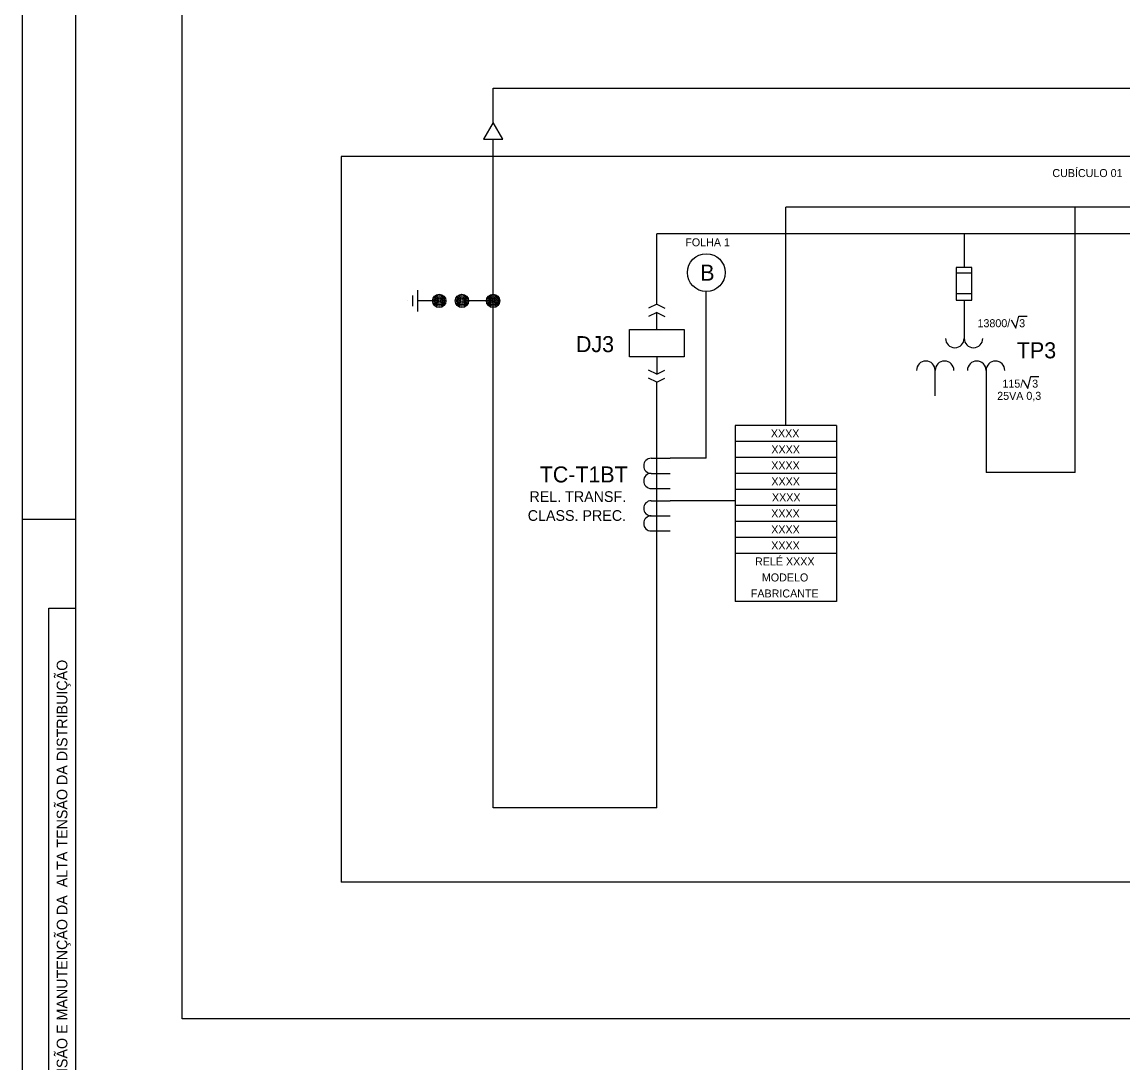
# Model space of a CAD drawing. Extents: x 563 to 1404, y 358 to 952.
# Drawn here: x 562.6 to 768.9, y 553.1 to 748.2 of the extents above; entities that cross this region are included whole.
import ezdxf

# ---------------------------------------------------------------- set-up
doc = ezdxf.new("R2010")
doc.units = 0
doc.layers.add('13', color=7, linetype='Continuous')
doc.layers.add('New Level (0)', color=7, linetype='Continuous')

# ---------------------------------------------------------------- blocks, each defined once
blk = doc.blocks.new('_U3')
for p, q in [((-1.47, 0.42), (-0.62, -1.12)), ((-0.62, -1.12), (-0.07, 1.12)), ((-0.07, 1.12), (1.47, 1.12))]:
    blk.add_line(p, q)

msp = doc.modelspace()

# ---------------------------------------------------------------- linework, layer by layer
for p, q in [((650.86, 729.31), (650.86, 735.75)), ((650.86, 735.75), (799.81, 735.75)), ((650.86, 729.31), (649.05, 726.21)), ((652.67, 726.21), (650.86, 729.31)), ((649.05, 726.21), (652.67, 726.21)), ((649.05, 726.21), (652.67, 726.21)), ((1296.89, 722.95), (622.37, 722.95)), ((622.37, 722.95), (622.37, 586.96)), ((1280.96, 713.45), (705.72, 713.45)), ((705.72, 672.55), (705.72, 713.45)), ((759.97, 663.73), (759.97, 713.45)), ((1256.75, 708.46), (681.52, 708.46)), ((681.52, 695.25), (681.52, 708.46)), ((739.14, 708.46), (739.14, 702.17)), ((740.6, 701.05), (737.67, 701.05)), ((636.77, 693.89), (636.77, 697.89)), ((690.82, 666.38), (690.82, 697.64)), ((634.77, 695.89), (634.77, 695.89)), ((635.77, 696.89), (635.77, 694.89)), ((640.77, 695.89), (636.77, 695.89)), ((640.77, 695.89), (636.77, 695.89)), ((650.86, 695.89), (646.27, 695.89)), ((740.6, 697.18), (737.67, 697.18)), ((739.14, 696.05), (739.14, 688.86)), ((681.52, 690.5), (681.52, 693.73)), ((681.52, 690.5), (681.52, 693.73)), ((676.4, 685.38), (676.4, 690.5)), ((676.4, 690.5), (686.64, 690.5)), ((686.64, 690.5), (686.64, 685.38)), ((686.64, 685.38), (676.4, 685.38)), ((681.52, 685.38), (681.52, 682.16)), ((733.71, 678.08), (733.71, 682.86)), ((743.25, 682.86), (743.25, 663.73)), ((681.52, 600.87), (681.52, 680.63)), ((715.21, 672.55), (696.23, 672.55)), ((696.23, 672.55), (696.23, 639.55)), ((715.21, 672.55), (715.21, 639.55)), ((715.21, 669.55), (696.23, 669.55)), ((715.21, 666.55), (696.23, 666.55)), ((680.5, 666.38), (684.03, 666.38)), ((690.82, 666.38), (684.03, 666.38)), ((680.5, 663.55), (684.03, 663.55)), ((715.21, 663.55), (696.23, 663.55)), ((759.97, 663.73), (743.25, 663.73)), ((680.5, 660.72), (684.03, 660.72)), ((715.21, 660.55), (696.23, 660.55)), ((680.5, 658.42), (684.03, 658.42)), ((696.23, 658.42), (684.03, 658.42)), ((715.21, 657.55), (696.23, 657.55)), ((680.5, 655.59), (684.03, 655.59)), ((715.21, 654.55), (696.23, 654.55)), ((715.21, 654.55), (696.23, 654.55)), ((680.5, 652.76), (684.03, 652.76)), ((715.21, 651.55), (696.23, 651.55)), ((715.21, 648.55), (696.23, 648.55)), ((715.21, 639.55), (696.23, 639.55)), ((1296.89, 586.96), (622.37, 586.96))]:
    msp.add_line(p, q)
msp.add_lwpolyline([(681.52, 600.87), (650.86, 600.87), (650.86, 726.21)])
msp.add_lwpolyline([(740.6, 702.17), (737.67, 702.17), (737.67, 696.05), (740.6, 696.05)], close=True)
for centre, radius in [((640.77, 695.89), 1.25), ((640.77, 695.89), 1), ((640.77, 695.89), 0.75), ((640.77, 695.89), 0.5), ((640.77, 695.89), 0.25), ((645.02, 695.89), 1.25), ((645.02, 695.89), 1), ((645.02, 695.89), 0.75), ((645.02, 695.89), 0.5), ((645.02, 695.89), 0.25), ((650.86, 695.89), 1.25), ((650.86, 695.89), 1), ((650.86, 695.89), 0.75), ((650.86, 695.89), 0.5), ((650.86, 695.89), 0.25)]:
    msp.add_circle(centre, radius)
for centre, radius, start, end in [((737.39, 688.86), 1.75, 180, 360), ((740.89, 688.86), 1.75, 180, 360), ((731.96, 682.86), 1.75, 0, 180), ((735.46, 682.86), 1.75, 0, 180), ((741.5, 682.86), 1.75, 0, 180), ((745, 682.86), 1.75, 0, 180), ((680.5, 664.97), 1.42, 90, 270), ((680.5, 662.14), 1.42, 90, 270), ((680.5, 657.01), 1.42, 90, 270), ((680.5, 654.18), 1.42, 90, 270)]:
    msp.add_arc(centre, radius, start, end)
at = {"layer": '13'}
for p, q in [((681.52, 695.25), (679.99, 694.49)), ((681.52, 693.73), (679.99, 692.97)), ((681.52, 695.25), (683.05, 694.49)), ((681.52, 693.73), (683.05, 692.97)), ((681.52, 682.16), (679.99, 682.92)), ((681.52, 680.63), (679.99, 681.4)), ((681.52, 682.16), (683.05, 682.92)), ((681.52, 680.63), (683.05, 681.4))]:
    msp.add_line(p, q, dxfattribs=at)
at = {"layer": 'New Level (0)'}
for p, q in [((562.58, 951.96), (562.58, 357.96)), ((562.58, 951.96), (562.58, 357.96)), ((572.58, 941.96), (572.58, 367.96)), ((572.58, 941.96), (572.58, 367.96)), ((562.58, 654.96), (572.58, 654.96)), ((567.58, 638.29), (572.58, 638.29)), ((567.58, 434.97), (567.58, 638.29))]:
    msp.add_line(p, q, dxfattribs=at)
msp.add_lwpolyline([(592.61, 760.21), (1379.09, 760.21), (1379.09, 561.33), (592.61, 561.33)], close=True, dxfattribs=at)
msp.add_circle((690.82, 701.18), 3.54, dxfattribs=at)

# ---------------------------------------------------------------- block references
for p in [(749.45, 691.92), (751.68, 680.6)]:
    msp.add_blockref('_U3', p)

# ---------------------------------------------------------------- texts
for s, height, p in [('CUBÍCULO 01', 1.5, (755.67, 719.09)), ('FOLHA 1', 1.5, (686.88, 706.11)), ('B', 3, (689.69, 699.68)), ('13800/   3', 1.5, (741.64, 690.95)), ('DJ3', 3, (666.39, 686.28)), ('TP3', 3, (749.02, 685.12)), ('115/   3', 1.5, (746.31, 679.63)), ('25VA 0,3', 1.5, (745.33, 677.34)), ('XXXX', 1.5, (702.91, 670.3)), ('XXXX', 1.5, (703.01, 667.3)), ('TC-T1BT', 3, (659.6, 661.86)), ('XXXX', 1.5, (702.98, 664.3)), ('XXXX', 1.5, (703.01, 661.3)), ('REL. TRANSF.', 2, (657.67, 658.21)), ('XXXX', 1.5, (703.12, 658.3)), ('CLASS. PREC.', 2, (657.35, 654.66)), ('XXXX', 1.5, (702.98, 655.3)), ('XXXX', 1.5, (702.98, 652.3)), ('XXXX', 1.5, (702.98, 649.3)), ('RELÉ XXXX', 1.5, (699.95, 646.3)), ('MODELO', 1.5, (701.23, 643.3)), ('FABRICANTE', 1.5, (699.16, 640.3))]:
    msp.add_text(s, height=height).set_placement(p)
msp.add_text('EA/EA - GERÊNCIA DE DE ESTRATÉGIA, CONTROLE, ESTUDOS E PROJETOS DA EXPANSÃO E MANUTENÇÃO DA  ALTA TENSÃO DA DISTRIBUIÇÃO', height=2, rotation=90, dxfattribs=at).set_placement((571.08, 438.56))

doc.saveas('drawing.dxf')
